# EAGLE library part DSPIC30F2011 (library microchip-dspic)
dsPIC Sensor DSP
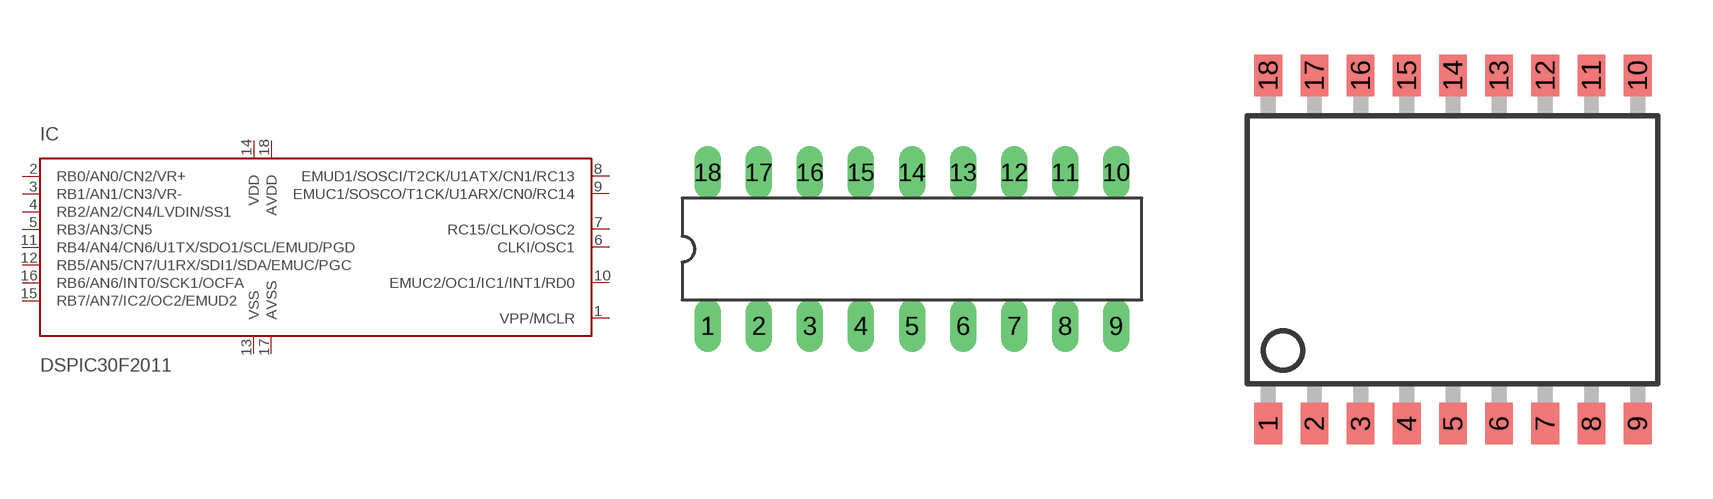
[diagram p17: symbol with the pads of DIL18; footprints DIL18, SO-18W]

Designator prefix IC

## DSPIC30F2011/P  [DIL18]
1  VPP/MCLR  in
2  RB0/AN0/CN2/VR+
3  RB1/AN1/CN3/VR-
4  RB2/AN2/CN4/LVDIN/SS1
5  RB3/AN3/CN5
6  CLKI/OSC1
7  RC15/CLKO/OSC2
8  EMUD1/SOSCI/T2CK/U1ATX/CN1/RC13
9  EMUC1/SOSCO/T1CK/U1ARX/CN0/RC14
10  EMUC2/OC1/IC1/INT1/RD0
11  RB4/AN4/CN6/U1TX/SDO1/SCL/EMUD/PGD
12  RB5/AN5/CN7/U1RX/SDI1/SDA/EMUC/PGC
13  VSS  pwr
14  VDD  pwr
15  RB7/AN7/IC2/OC2/EMUD2
16  RB6/AN6/INT0/SCK1/OCFA
17  AVSS  pwr
18  AVDD  pwr

## DSPIC30F2011/SO  [SO-18W]
Pads as for DIL18

## DSPIC30F2011/ML  [QFN-S28-6X6]
1  RB2/AN2/CN4/LVDIN/SS1
2  RB3/AN3/CN5
5  VSS  pwr
6  CLKI/OSC1
7  RC15/CLKO/OSC2
8  EMUD1/SOSCI/T2CK/U1ATX/CN1/RC13
9  EMUC1/SOSCO/T1CK/U1ARX/CN0/RC14
10  VDD  pwr
12  EMUC2/OC1/IC1/INT1/RD0
14  RB4/AN4/CN6/U1TX/SDO1/SCL/EMUD/PGD
15  RB5/AN5/CN7/U1RX/SDI1/SDA/EMUC/PGC
22  RB7/AN7/IC2/OC2/EMUD2
23  RB6/AN6/INT0/SCK1/OCFA
24  AVSS  pwr
25  AVDD  pwr
26  VPP/MCLR  in
27  RB0/AN0/CN2/VR+
28  RB1/AN1/CN3/VR-

## Footprint DIL18 (pad centres in mm)
Dual In Line package type P
drill 0.813 long: 1 -10.16,-3.81; 2 -7.62,-3.81; 3 -5.08,-3.81; 4 -2.54,-3.81; 5 0,-3.81; 6 2.54,-3.81; 7 5.08,-3.81; 8 7.62,-3.81; 9 10.16,-3.81; 10 10.16,3.81; 11 7.62,3.81; 12 5.08,3.81; 13 2.54,3.81; 14 0,3.81; 15 -2.54,3.81; 16 -5.08,3.81; 17 -7.62,3.81; 18 -10.16,3.81

## Footprint SO-18W (pad centres in mm)
Small Outline Wide Plastic Gull Wing 300-mil body, package type SO
smd 0.762 x 1.143: 1 -5.08,-4.788; 2 -3.81,-4.788; 3 -2.54,-4.788; 4 -1.27,-4.788; 5 0,-4.788; 6 1.27,-4.788; 7 2.54,-4.788; 8 3.81,-4.788; 9 5.08,-4.788; 10 5.08,4.788; 11 3.81,4.788; 12 2.54,4.788; 13 1.27,4.788; 14 0,4.788; 15 -1.27,4.788; 16 -2.54,4.788; 17 -3.81,4.788; 18 -5.08,4.788

## Footprint QFN-S28-6X6 (pad centres in mm)
Quad Flat No Lead
smd 0.6 x 0.4: 1 2.75,-1.95; 2 2.75,-1.3; 3 2.75,-0.65; 4 2.75,0; 5 2.75,0.65; 6 2.75,1.3; 7 2.75,1.95; 15 -2.75,1.95; 16 -2.75,1.3; 17 -2.75,0.65; 18 -2.75,0; 19 -2.75,-0.65; 20 -2.75,-1.3; 21 -2.75,-1.95
smd 0.4 x 0.6: 8 1.95,2.75; 9 1.3,2.75; 10 0.65,2.75; 11 0,2.75; 12 -0.65,2.75; 13 -1.3,2.75; 14 -1.95,2.75; 22 -1.95,-2.75; 23 -1.3,-2.75; 24 -0.65,-2.75; 25 0,-2.75; 26 0.65,-2.75; 27 1.3,-2.75; 28 1.95,-2.75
